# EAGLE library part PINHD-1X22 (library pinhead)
PIN HEADER
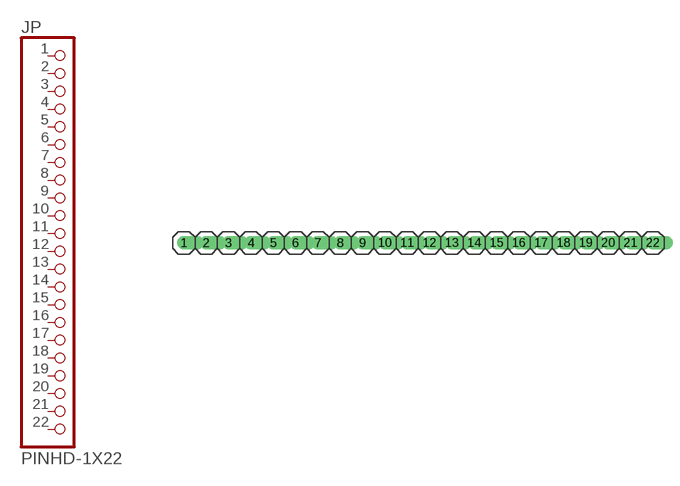
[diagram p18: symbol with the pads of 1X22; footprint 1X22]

Designator prefix JP

## PINHD-1X22  [1X22]
1  1  pas
2  2  pas
3  3  pas
4  4  pas
5  5  pas
6  6  pas
7  7  pas
8  8  pas
9  9  pas
10  10  pas
11  11  pas
12  12  pas
13  13  pas
14  14  pas
15  15  pas
16  16  pas
17  17  pas
18  18  pas
19  19  pas
20  20  pas
21  21  pas
22  22  pas

## Footprint 1X22 (pad centres in mm)
PIN HEADER
drill 1.016 offset: 1 -26.67,0; 2 -24.13,0; 3 -21.59,0; 4 -19.05,0; 5 -16.51,0; 6 -13.97,0; 7 -11.43,0; 8 -8.89,0; 9 -6.35,0; 10 -3.81,0; 11 -1.27,0; 12 1.27,0; 13 3.81,0; 14 6.35,0; 15 8.89,0; 16 11.43,0; 17 13.97,0; 18 16.51,0; 19 19.05,0; 20 21.59,0; 21 24.13,0; 22 26.67,0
